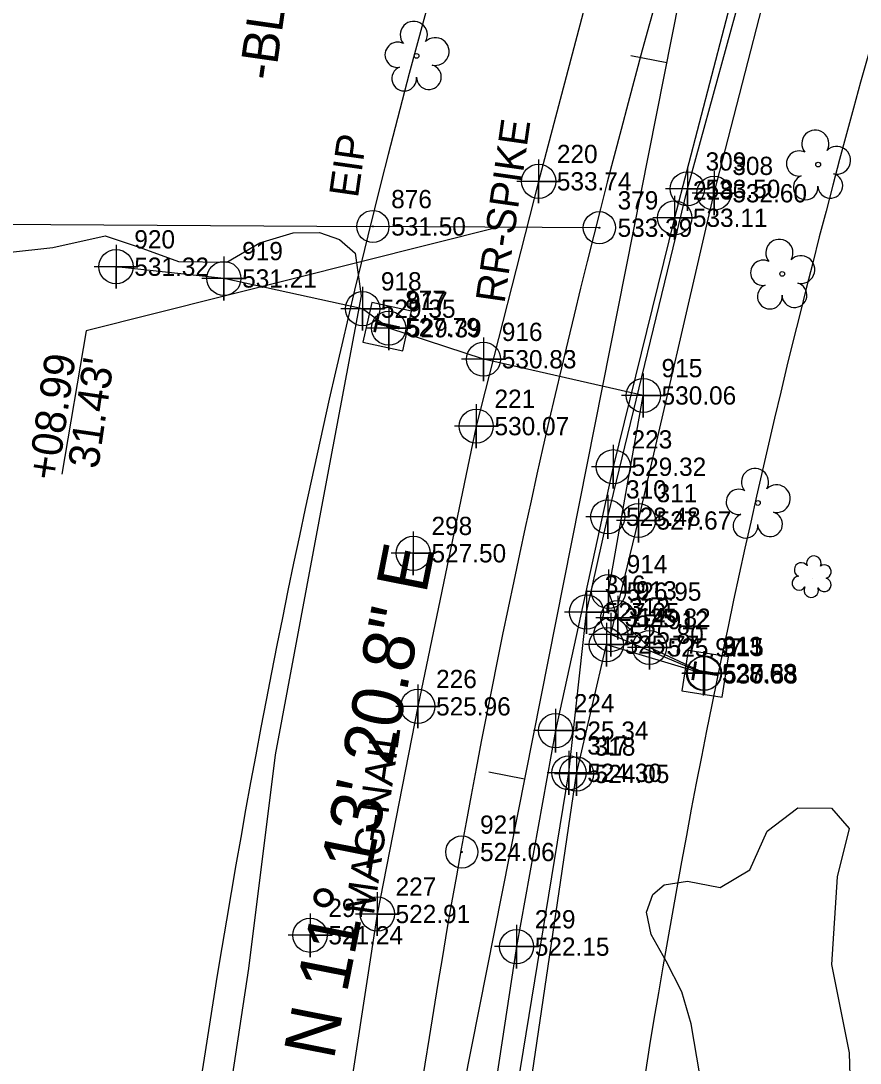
# Model space of a CAD drawing. Extents: x 1698744 to 1699848, y 707609 to 709748.
# Drawn here: x 1699376.8 to 1699491.7, y 709032.6 to 709175.3 of the extents above; entities that cross this region are included whole.
import ezdxf

# ---------------------------------------------------------------- set-up
doc = ezdxf.new("R2010")
doc.units = 0
for name, color, linetype in [('CTL Bench Mark Text', 7, 'Continuous'), ('Default Symbol CELL', 7, 'Continuous'), ('Default Symbol Cogo Elevation', 7, 'Continuous'), ('Default Symbol Cogo Number', 7, 'Continuous'), ('Exist Horizontal Alignment', 7, 'Continuous'), ('Exist Horizontal Baseline Alignment', 7, 'Continuous'), ('Exist Horizontal Baseline Alignment Direction Label', 7, 'Continuous'), ('Exist Horizontal Baseline Alignment Tick small', 7, 'Continuous'), ('Exist Property Iron Pin Text', 7, 'Continuous'), ('Exist Property Line', 7, 'Continuous'), ('Exist Property Tie Line', 7, 'Continuous'), ('Exist Property Tie Line Leader', 7, 'Continuous'), ('Exist Right of Way Line', 7, 'Continuous'), ('Exist Utilities Telephone UG Cable', 7, 'Continuous'), ('Exist Vegetation Shrub CELL', 7, 'Continuous'), ('Exist Vegetation Tree CELL', 7, 'Continuous'), ('Exist Vegetation Woods Line', 7, 'Continuous'), ('Prop Approach Slab', 7, 'Continuous'), ('Prop Approach Slab Hatching', 7, 'Continuous'), ('Prop Conc Shoulder Berm Gutter', 7, 'Continuous'), ('Prop Horizontal Alignment Station Label', 7, 'Continuous'), ('Prop North Arrow NAD83 for Plan Sheets CELL', 7, 'Continuous'), ('Prop Roadway Bridge', 7, 'Continuous'), ('Prop Structure Anchor Unit CELL', 7, 'Continuous'), ('Prop Superelevation  Arrow CELL', 7, 'Continuous'), ('Prop Superelevation Label', 7, 'Continuous'), ('Sheet Border Standard 30in CELL', 7, 'Continuous'), ('Sheet Data Field CELL', 7, 'Continuous'), ('Sheet Plot Border Inside CELL', 7, 'Continuous'), ('Sheet Sticker Preliminary CELL', 7, 'Continuous')]:
    doc.layers.add(name, color=color, linetype=linetype)

msp = doc.modelspace()

# ---------------------------------------------------------------- linework, layer by layer
at = {"layer": 'Default Symbol CELL'}
for points in [[(1699430.5, 709105.37), (1699430.5, 709099.37), (1699430.5, 709102.37), (1699433.5, 709102.37), (1699427.5, 709102.37)], [(1699416.37, 709053.07), (1699416.37, 709047.07), (1699416.37, 709050.07), (1699419.37, 709050.07), (1699413.37, 709050.07)]]:
    msp.add_lwpolyline(points, dxfattribs=at)
for centre in [(1699430.5, 709102.37), (1699416.37, 709050.07)]:
    msp.add_circle(centre, 2.34, dxfattribs=at)
at = {"layer": 'Exist Horizontal Alignment'}
msp.add_arc((1700689.97, 708835.23), 1273.24, 164.19229, 174.9628, dxfattribs=at)
at = {"layer": 'Exist Horizontal Baseline Alignment'}
msp.add_line((1699395.77, 708819.44), (1699513.15, 709411.06), dxfattribs=at)
at = {"layer": 'Exist Horizontal Baseline Alignment Tick small'}
for p, q in [((1699465.22, 709169.51), (1699460.32, 709170.48)), ((1699445.76, 709071.42), (1699440.86, 709072.39))]:
    msp.add_line(p, q, dxfattribs=at)
at = {"layer": 'Exist Property Line'}
msp.add_line((1698964.53, 709149.77), (1699424.6, 709147.13), dxfattribs=at)
at = {"layer": 'Exist Property Tie Line'}
msp.add_line((1699456.03, 709146.95), (1699424.6, 709147.13), dxfattribs=at)
at = {"layer": 'Exist Property Tie Line Leader'}
msp.add_lwpolyline([(1699442.02, 709146.96), (1699385.69, 709132.83), (1699382.36, 709113.22)], dxfattribs=at)
at = {"layer": 'Exist Right of Way Line'}
for radius in [1303.24, 1243.24]:
    msp.add_arc((1700689.97, 708835.23), radius, 164.19229, 174.9628, dxfattribs=at)
at = {"layer": 'Exist Utilities Telephone UG Cable'}
for points in [[(1699441.75, 708843.06), (1699433.58, 708844.03), (1699428.5, 708846.07), (1699429.26, 708856.44), (1699434.77, 708937.33), (1699437.75, 708973.12), (1699443.66, 709022.32), (1699451.83, 709072.31), (1699454.23, 709094.33), (1699457.14, 709107.37), (1699468.04, 709152.27), (1699491.2, 709236.57), (1699501.58, 709271.54), (1699517.86, 709327.49), (1699534.26, 709386.49)], [(1699441.69, 708843.63), (1699436.49, 708849.12), (1699431.56, 708856.83), (1699436.15, 708937.18), (1699439.02, 708973.24), (1699445.51, 709022.28), (1699452.85, 709072.16), (1699456.95, 709089.86), (1699470.27, 709085.91), (1699457.57, 709091.24), (1699461.33, 709106.86), (1699471.7, 709151.67), (1699493.37, 709235.72), (1699503.07, 709271.03), (1699519.14, 709327.08), (1699535.26, 709386.02)], [(1699470.38, 709085.97), (1699462.85, 709089.48), (1699458.51, 709093.55), (1699457.24, 709097.13), (1699462.01, 709123.98), (1699440.13, 709128.94), (1699427.14, 709133.19), (1699423.57, 709135.86), (1699404.57, 709140), (1699389.8, 709141.61)]]:
    msp.add_lwpolyline(points, dxfattribs=at)
at = {"layer": 'Exist Vegetation Shrub CELL'}
msp.add_line((1699485.14, 709098.98), (1699485.14, 709098.98), dxfattribs=at)
for centre, radius, start, end in [((1699485.37, 709101.02), 0.99, 334.8391, 200.4717), ((1699483.66, 709100.11), 0.968, 35.8908, 245.4216), ((1699486.81, 709099.85), 0.929, 284.4567, 126.0861), ((1699483.34, 709098.28), 0.955, 95.1099, 327.9534), ((1699485.01, 709097.3), 0.984, 151.2797, 21.387), ((1699486.78, 709098.05), 0.937, 204.9913, 73.4601)]:
    msp.add_arc(centre, radius, start, end, dxfattribs=at)
at = {"layer": 'Exist Vegetation Tree CELL'}
for p, q in [((1699430.96, 709170.48), (1699430.96, 709170.48)), ((1699485.96, 709155.59), (1699485.96, 709155.59)), ((1699481.04, 709140.63), (1699481.04, 709140.63)), ((1699477.7, 709109.26), (1699477.7, 709109.26))]:
    msp.add_line(p, q, dxfattribs=at)
for centre in [(1699430.96, 709170.48), (1699485.96, 709155.59), (1699481.04, 709140.63), (1699477.7, 709109.26)]:
    msp.add_circle(centre, 0.326, dxfattribs=at)
for centre, radius, start, end in [((1699430.58, 709173.35), 1.86, 330.1651, 219.7134), ((1699428.36, 709170.63), 1.73, 62.6636, 279.3457), ((1699433.51, 709171.07), 1.9, 257.1011, 134.1999), ((1699429.26, 709167.36), 1.69, 111.5671, 6.231), ((1699432.64, 709167.58), 1.7, 181.2822, 74.56), ((1699485.57, 709158.46), 1.86, 330.1651, 219.7134), ((1699488.5, 709156.18), 1.9, 257.1011, 134.1999), ((1699483.35, 709155.74), 1.73, 62.6636, 279.3457), ((1699484.25, 709152.47), 1.69, 111.5671, 6.231), ((1699487.63, 709152.69), 1.7, 181.2822, 74.56), ((1699480.65, 709143.5), 1.86, 330.1651, 219.7134), ((1699478.43, 709140.78), 1.73, 62.6636, 279.3457), ((1699483.59, 709141.21), 1.9, 257.1011, 134.1999), ((1699479.33, 709137.51), 1.69, 111.5671, 6.231), ((1699482.71, 709137.73), 1.7, 181.2822, 74.56), ((1699477.31, 709112.13), 1.86, 330.1651, 219.7134), ((1699475.09, 709109.41), 1.73, 62.6636, 279.3457), ((1699480.25, 709109.85), 1.9, 257.1011, 134.1999), ((1699476, 709106.14), 1.69, 111.5671, 6.231), ((1699479.37, 709106.36), 1.7, 181.2822, 74.56)]:
    msp.add_arc(centre, radius, start, end, dxfattribs=at)
at = {"layer": 'Exist Vegetation Woods Line'}
for points in [[(1699353.45, 709143.25), (1699353.63, 709143.25), (1699369.07, 709142.91), (1699381.14, 709144.22), (1699388.31, 709145.82), (1699392.97, 709144.28), (1699398.36, 709142.32), (1699404.95, 709142.25), (1699409.47, 709144.86), (1699414.04, 709146.24), (1699417.66, 709146.31), (1699420.39, 709145.35), (1699422.57, 709143.47), (1699423.36, 709137.6), (1699418.47, 709111.67), (1699411.61, 709074.77), (1699407.92, 709045.52), (1699401.9, 709005.83)], [(1699469.77, 709030.97), (1699468.55, 709037.94), (1699467.3, 709042.33), (1699465.14, 709046.53), (1699463.09, 709050.18), (1699462.43, 709053.22), (1699463.32, 709055.64), (1699464.87, 709056.99), (1699468.08, 709057.49), (1699472.54, 709056.61), (1699476.58, 709059.03), (1699478.98, 709064.3), (1699483.18, 709067.5), (1699487.8, 709067.45), (1699490.19, 709064.67), (1699488.54, 709058.08), (1699487.78, 709046.06), (1699490.21, 709033.97), (1699490.54, 709022.93)]]:
    msp.add_lwpolyline(points, dxfattribs=at)
at = {"layer": 'Prop Approach Slab'}
for p, q in [((1699426.9, 709133.33), (1699426.9, 709133.33)), ((1699470.43, 709085.78), (1699470.43, 709085.78))]:
    msp.add_line(p, q, dxfattribs=at)
for points in [[(1699429.08, 709130.07), (1699430.28, 709135.53), (1699424.81, 709136.72), (1699423.62, 709131.26), (1699429.08, 709130.07)], [(1699472.8, 709082.65), (1699473.68, 709088.17), (1699468.15, 709089.05), (1699467.27, 709083.53), (1699472.8, 709082.65)]]:
    msp.add_lwpolyline(points, dxfattribs=at)
at = {"layer": 'Prop Horizontal Alignment Station Label'}
for centre, radius in [((1699424.98, 709147.12), 2.2), ((1699455.99, 709146.95), 2.2), ((1699424.98, 709147.12), 0.0707), ((1699455.99, 709146.95), 0.0707), ((1699437.15, 709061.47), 2.2), ((1699437.15, 709061.47), 0.0707)]:
    msp.add_circle(centre, radius, dxfattribs=at)
at = {"layer": 'Prop North Arrow NAD83 for Plan Sheets CELL'}
for points in [[(1699468.04, 709155.27), (1699468.04, 709149.27), (1699468.04, 709152.27), (1699471.04, 709152.27), (1699465.04, 709152.27)], [(1699471.7, 709154.67), (1699471.7, 709148.67), (1699471.7, 709151.67), (1699474.7, 709151.67), (1699468.7, 709151.67)], [(1699389.8, 709144.61), (1699389.8, 709138.61), (1699389.8, 709141.61), (1699392.8, 709141.61), (1699386.8, 709141.61)], [(1699404.57, 709143), (1699404.57, 709137), (1699404.57, 709140), (1699407.57, 709140), (1699401.57, 709140)], [(1699423.57, 709138.86), (1699423.57, 709132.86), (1699423.57, 709135.86), (1699426.57, 709135.86), (1699420.57, 709135.86)], [(1699427.14, 709136.19), (1699427.14, 709130.19), (1699427.14, 709133.19), (1699430.14, 709133.19), (1699424.14, 709133.19)], [(1699440.13, 709131.94), (1699440.13, 709125.94), (1699440.13, 709128.94), (1699443.13, 709128.94), (1699437.13, 709128.94)], [(1699462.01, 709126.98), (1699462.01, 709120.98), (1699462.01, 709123.98), (1699465.01, 709123.98), (1699459.01, 709123.98)], [(1699457.14, 709110.37), (1699457.14, 709104.37), (1699457.14, 709107.37), (1699460.14, 709107.37), (1699454.14, 709107.37)], [(1699461.33, 709109.86), (1699461.33, 709103.86), (1699461.33, 709106.86), (1699464.33, 709106.86), (1699458.33, 709106.86)], [(1699457.24, 709100.13), (1699457.24, 709094.13), (1699457.24, 709097.13), (1699460.24, 709097.13), (1699454.24, 709097.13)], [(1699454.23, 709097.33), (1699454.23, 709091.33), (1699454.23, 709094.33), (1699457.23, 709094.33), (1699451.23, 709094.33)], [(1699458.51, 709096.55), (1699458.51, 709090.55), (1699458.51, 709093.55), (1699461.51, 709093.55), (1699455.51, 709093.55)], [(1699457.57, 709094.24), (1699457.57, 709088.24), (1699457.57, 709091.24), (1699460.57, 709091.24), (1699454.57, 709091.24)], [(1699456.95, 709092.86), (1699456.95, 709086.86), (1699456.95, 709089.86), (1699459.95, 709089.86), (1699453.95, 709089.86)], [(1699462.85, 709092.48), (1699462.85, 709086.48), (1699462.85, 709089.48), (1699465.85, 709089.48), (1699459.85, 709089.48)], [(1699470.27, 709088.91), (1699470.27, 709082.91), (1699470.27, 709085.91), (1699473.27, 709085.91), (1699467.27, 709085.91)], [(1699470.38, 709088.97), (1699470.38, 709082.97), (1699470.38, 709085.97), (1699473.38, 709085.97), (1699467.38, 709085.97)], [(1699451.83, 709075.31), (1699451.83, 709069.31), (1699451.83, 709072.31), (1699454.83, 709072.31), (1699448.83, 709072.31)], [(1699452.85, 709075.16), (1699452.85, 709069.16), (1699452.85, 709072.16), (1699455.85, 709072.16), (1699449.85, 709072.16)]]:
    msp.add_lwpolyline(points, dxfattribs=at)
for centre in [(1699468.04, 709152.27), (1699471.7, 709151.67), (1699389.8, 709141.61), (1699404.57, 709140), (1699423.57, 709135.86), (1699427.14, 709133.19), (1699440.13, 709128.94), (1699462.01, 709123.98), (1699457.14, 709107.37), (1699461.33, 709106.86), (1699457.24, 709097.13), (1699454.23, 709094.33), (1699458.51, 709093.55), (1699457.57, 709091.24), (1699456.95, 709089.86), (1699462.85, 709089.48), (1699470.27, 709085.91), (1699470.38, 709085.97), (1699451.83, 709072.31), (1699452.85, 709072.16)]:
    msp.add_circle(centre, 2.34, dxfattribs=at)
at = {"layer": 'Sheet Border Standard 30in CELL'}
for points in [[(1699447.67, 709156.3), (1699447.67, 709150.3), (1699447.67, 709153.3), (1699450.67, 709153.3), (1699444.67, 709153.3)], [(1699466.3, 709151.31), (1699466.3, 709145.31), (1699466.3, 709148.31), (1699469.3, 709148.31), (1699463.3, 709148.31)], [(1699439.13, 709122.78), (1699439.13, 709116.78), (1699439.13, 709119.78), (1699442.13, 709119.78), (1699436.13, 709119.78)], [(1699457.9, 709117.22), (1699457.9, 709111.22), (1699457.9, 709114.22), (1699460.9, 709114.22), (1699454.9, 709114.22)], [(1699431.13, 709084.41), (1699431.13, 709078.41), (1699431.13, 709081.41), (1699434.13, 709081.41), (1699428.13, 709081.41)], [(1699449.99, 709081.09), (1699449.99, 709075.09), (1699449.99, 709078.09), (1699452.99, 709078.09), (1699446.99, 709078.09)], [(1699425.58, 709055.98), (1699425.58, 709049.98), (1699425.58, 709052.98), (1699428.58, 709052.98), (1699422.58, 709052.98)], [(1699444.65, 709051.51), (1699444.65, 709045.51), (1699444.65, 709048.51), (1699447.65, 709048.51), (1699441.65, 709048.51)]]:
    msp.add_lwpolyline(points, dxfattribs=at)
for centre in [(1699447.67, 709153.3), (1699466.3, 709148.31), (1699439.13, 709119.78), (1699457.9, 709114.22), (1699431.13, 709081.41), (1699449.99, 709078.09), (1699425.58, 709052.98), (1699444.65, 709048.51)]:
    msp.add_circle(centre, 2.34, dxfattribs=at)
at = {"layer": 'Sheet Sticker Preliminary CELL'}
for points in [[(1699523.53, 709430.62), (1699509.87, 709380.4), (1699496.34, 709331.75), (1699485.4, 709292.12), (1699472.33, 709243.96), (1699460.09, 709200.29), (1699447.67, 709153.3), (1699439.13, 709119.78), (1699431.13, 709081.41), (1699425.58, 709052.98), (1699419.28, 709011.91), (1699415.32, 708978.51), (1699411.44, 708941.68), (1699408.45, 708907.15), (1699404.87, 708864.71), (1699401.1, 708830.74), (1699396.87, 708803.49)], [(1699542.38, 709424.6), (1699528.69, 709374.56), (1699515.83, 709327.15), (1699504.48, 709285.96), (1699491.02, 709238.81), (1699478.11, 709193.7), (1699466.3, 709148.31), (1699457.9, 709114.22), (1699449.99, 709078.09), (1699444.65, 709048.51), (1699438.62, 709008.95), (1699434.24, 708974.87), (1699430.76, 708939.89), (1699427.59, 708904.74), (1699424.05, 708863.15), (1699421.85, 708827.25), (1699420.58, 708799.94)]]:
    msp.add_lwpolyline(points, dxfattribs=at)

# ---------------------------------------------------------------- texts
at = {"layer": 'CTL Bench Mark Text'}
msp.add_text('-BL- STA 14+48.35', height=5, rotation=81.8738, dxfattribs=at).set_placement((1699411.55, 709166.97))
at = {"layer": 'Default Symbol Cogo Elevation'}
for s, p in [('527.50', (1699433, 709101.12)), ('521.24', (1699418.87, 709048.82))]:
    msp.add_text(s, height=2.5, dxfattribs=at).set_placement(p)
at = {"layer": 'Default Symbol Cogo Number'}
for s, p in [('298', (1699433, 709104.87)), ('297', (1699418.87, 709052.57))]:
    msp.add_text(s, height=2.5, dxfattribs=at).set_placement(p)
at = {"layer": 'Exist Horizontal Baseline Alignment Direction Label'}
msp.add_text('N 11%%d 13\' 20.8" E', height=7, rotation=78.7775, dxfattribs=at).set_placement((1699419.59, 709032.87))
at = {"layer": 'Exist Property Iron Pin Text'}
for s, p in [('RR-SPIKE', (1699442.99, 709136.49)), ('EIP', (1699422.92, 709150.93)), ('MAG-NAIL', (1699425.1, 709052.71))]:
    msp.add_text(s, height=4, rotation=81.8738, dxfattribs=at).set_placement(p)
at = {"layer": 'Exist Property Tie Line Leader'}
for s, p in [('+08.99', (1699381.79, 709112.22)), ("31.43'", (1699387.34, 709113.81))]:
    msp.add_text(s, height=4.2, rotation=81.6683, dxfattribs=at).set_placement(p)
at = {"layer": 'Prop Approach Slab'}
for rotation, p in [(77.6983, (1699428.34, 709131.86)), (80.9756, (1699471.95, 709084.4))]:
    msp.add_text('T', height=3.42, rotation=rotation, dxfattribs=at).set_placement(p)
at = {"layer": 'Prop Approach Slab Hatching'}
for s, p in [('877', (1699429.4, 709135.83)), ('315', (1699472.93, 709088.28))]:
    msp.add_text(s, height=2.5, dxfattribs=at).set_placement(p)
at = {"layer": 'Prop Conc Shoulder Berm Gutter'}
for s, p in [('531.50', (1699427.48, 709145.87)), ('533.39', (1699458.49, 709145.7)), ('524.06', (1699439.65, 709060.22))]:
    msp.add_text(s, height=2.5, dxfattribs=at).set_placement(p)
at = {"layer": 'Prop Roadway Bridge'}
for s, p in [('533.50', (1699470.54, 709151.02)), ('532.60', (1699474.2, 709150.42)), ('531.32', (1699392.3, 709140.36)), ('531.21', (1699407.07, 709138.75)), ('529.35', (1699426.07, 709134.61)), ('529.39', (1699429.64, 709131.94)), ('530.83', (1699442.63, 709127.69)), ('530.06', (1699464.51, 709122.73)), ('528.48', (1699459.64, 709106.12)), ('527.67', (1699463.83, 709105.61)), ('526.95', (1699459.74, 709095.88)), ('527.05', (1699456.73, 709093.08)), ('525.82', (1699461.01, 709092.3)), ('525.80', (1699460.07, 709089.99)), ('525.77', (1699459.45, 709088.61)), ('525.97', (1699465.35, 709088.23)), ('528.68', (1699472.77, 709084.66)), ('527.58', (1699472.88, 709084.72)), ('524.30', (1699454.33, 709071.06)), ('524.05', (1699455.35, 709070.91))]:
    msp.add_text(s, height=2.5, dxfattribs=at).set_placement(p)
at = {"layer": 'Prop Structure Anchor Unit CELL'}
for s, p in [('527.79', (1699429.4, 709132.08)), ('530.83', (1699472.93, 709084.53))]:
    msp.add_text(s, height=2.5, dxfattribs=at).set_placement(p)
at = {"layer": 'Prop Superelevation  Arrow CELL'}
for s, p in [('876', (1699427.48, 709149.62)), ('379', (1699458.49, 709149.45)), ('921', (1699439.65, 709063.97))]:
    msp.add_text(s, height=2.5, dxfattribs=at).set_placement(p)
at = {"layer": 'Prop Superelevation Label'}
for s, p in [('309', (1699470.54, 709154.77)), ('308', (1699474.2, 709154.17)), ('920', (1699392.3, 709144.11)), ('919', (1699407.07, 709142.5)), ('918', (1699426.07, 709138.36)), ('917', (1699429.64, 709135.69)), ('916', (1699442.63, 709131.44)), ('915', (1699464.51, 709126.48)), ('310', (1699459.64, 709109.87)), ('311', (1699463.83, 709109.36)), ('914', (1699459.74, 709099.63)), ('316', (1699456.73, 709096.83)), ('913', (1699461.01, 709096.05)), ('312', (1699460.07, 709093.74)), ('314', (1699459.45, 709092.36)), ('912', (1699465.35, 709091.98)), ('313', (1699472.77, 709088.41)), ('911', (1699472.88, 709088.47)), ('317', (1699454.33, 709074.81)), ('318', (1699455.35, 709074.66))]:
    msp.add_text(s, height=2.5, dxfattribs=at).set_placement(p)
at = {"layer": 'Sheet Data Field CELL'}
for s, p in [('220', (1699450.17, 709155.8)), ('218', (1699468.8, 709150.81)), ('221', (1699441.63, 709122.28)), ('223', (1699460.4, 709116.72)), ('226', (1699433.63, 709083.91)), ('224', (1699452.49, 709080.59)), ('227', (1699428.08, 709055.48)), ('229', (1699447.15, 709051.01))]:
    msp.add_text(s, height=2.5, dxfattribs=at).set_placement(p)
at = {"layer": 'Sheet Plot Border Inside CELL'}
for s, p in [('533.74', (1699450.17, 709152.05)), ('533.11', (1699468.8, 709147.06)), ('530.07', (1699441.63, 709118.53)), ('529.32', (1699460.4, 709112.97)), ('525.96', (1699433.63, 709080.16)), ('525.34', (1699452.49, 709076.84)), ('522.91', (1699428.08, 709051.73)), ('522.15', (1699447.15, 709047.26))]:
    msp.add_text(s, height=2.5, dxfattribs=at).set_placement(p)

doc.saveas('drawing.dxf')
